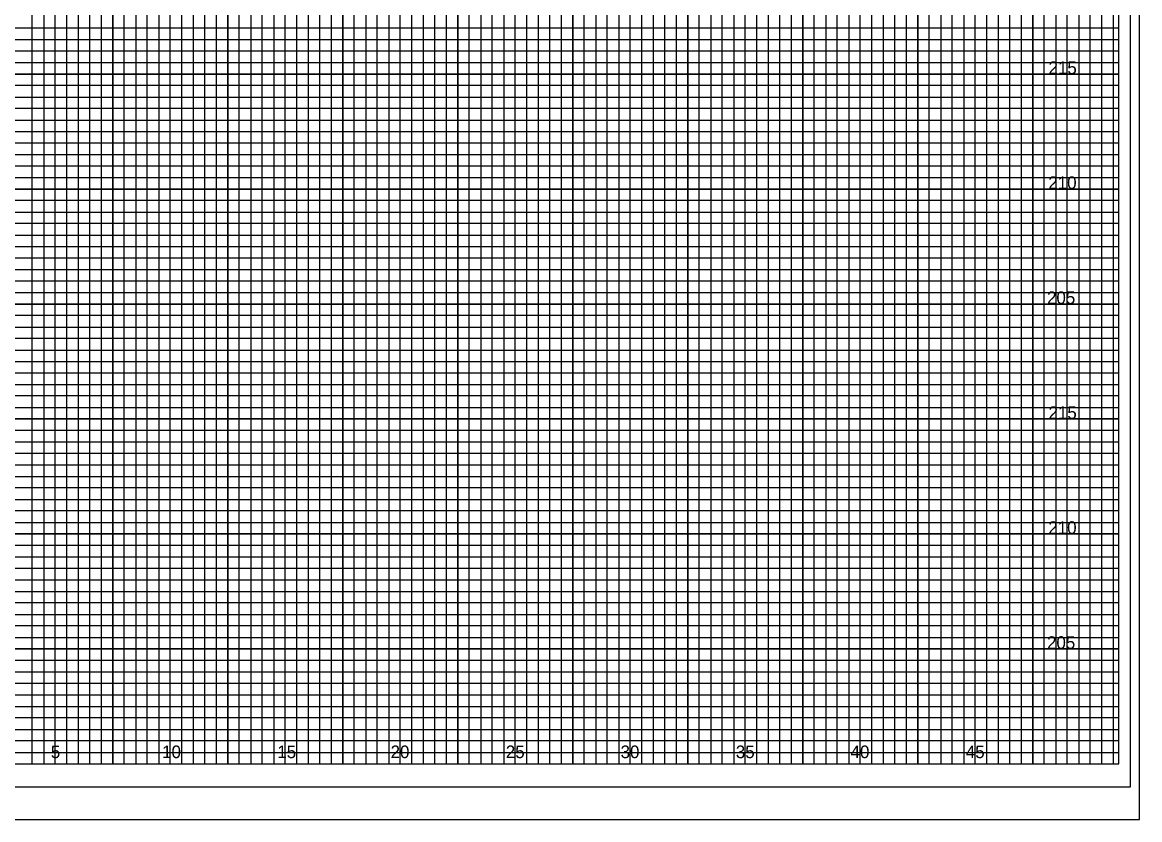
# Model space of a CAD drawing. Extents: x -4 to 103, y -2 to 209.
# Drawn here: x 54.82 to 103.4, y -2.43 to 32.25 of the extents above; entities that cross this region are included whole.
import ezdxf

# ---------------------------------------------------------------- set-up
doc = ezdxf.new("R2010")
doc.units = 0
for name, color, linetype in [('Old_Level_10', 7, 'Continuous'), ('Old_Level_16', 7, 'Continuous'), ('Old_Level_17', 7, 'Continuous'), ('Old_Level_3', 7, 'Continuous'), ('Old_Level_5', 7, 'Continuous'), ('Old_Level_6', 7, 'Continuous'), ('Old_Level_8', 7, 'Continuous'), ('Prop Dimension', 7, 'Continuous'), ('Typical Curb CELL', 7, 'Continuous')]:
    doc.layers.add(name, color=color, linetype=linetype)

msp = doc.modelspace()

# ---------------------------------------------------------------- linework, layer by layer
at = {"layer": 'Old_Level_10'}
for p, q in [((56.25, 0), (56.25, 65)), ((58.75, 0), (58.75, 65)), ((61.25, 0), (61.25, 65)), ((63.75, 0), (63.75, 65)), ((66.25, 0), (66.25, 65)), ((68.75, 0), (68.75, 65)), ((71.25, 0), (71.25, 65)), ((73.75, 0), (73.75, 65)), ((91.25, 0), (91.25, 63.425)), ((93.75, 0), (93.75, 63.425)), ((96.25, 0), (96.25, 63.425)), ((98.75, 0), (98.75, 63.425)), ((101.25, 0), (101.25, 63.425)), ((76.25, 0), (76.25, 62)), ((78.75, 0), (78.75, 62)), ((81.25, 0), (81.25, 62)), ((83.75, 0), (83.75, 62)), ((86.25, 0), (86.25, 62)), ((88.75, 0), (88.75, 62)), ((0, 30), (102.5, 30)), ((0, 27.5), (102.5, 27.5)), ((0, 25), (102.5, 25)), ((0, 22.5), (102.5, 22.5)), ((0, 20), (102.5, 20)), ((0, 17.5), (102.5, 17.5)), ((0, 15), (102.5, 15)), ((0, 12.5), (102.5, 12.5)), ((0, 10), (102.5, 10)), ((0, 7.5), (102.5, 7.5)), ((0, 5), (102.5, 5)), ((0, 2.5), (102.5, 2.5))]:
    msp.add_line(p, q, dxfattribs=at)
at = {"layer": 'Old_Level_17'}
for points in [[(54.75, 0), (55.25, 0), (55.25, 65)], [(55.75, 65), (55.75, 0), (56.75, 0), (56.75, 65)], [(57.25, 65), (57.25, 0), (57.75, 0), (57.75, 65)], [(58.25, 65), (58.25, 0), (59.25, 0), (59.25, 65)], [(59.75, 65), (59.75, 0), (60.25, 0), (60.25, 65)], [(60.75, 65), (60.75, 0), (61.75, 0), (61.75, 65)], [(62.25, 65), (62.25, 0), (62.75, 0), (62.75, 65)], [(63.25, 65), (63.25, 0), (64.25, 0), (64.25, 65)], [(64.75, 65), (64.75, 0), (65.25, 0), (65.25, 65)], [(65.75, 65), (65.75, 0), (66.75, 0), (66.75, 65)], [(67.25, 65), (67.25, 0), (67.75, 0), (67.75, 65)], [(68.25, 65), (68.25, 0), (69.25, 0), (69.25, 65)], [(69.75, 65), (69.75, 0), (70.25, 0), (70.25, 65)], [(70.75, 65), (70.75, 0), (71.75, 0), (71.75, 65)], [(72.25, 65), (72.25, 0), (72.75, 0), (72.75, 65)], [(73.25, 65), (73.25, 0), (74.25, 0), (74.25, 62)], [(89.75, 62), (89.75, 0), (90.25, 0), (90.25, 63.425)], [(90.75, 63.425), (90.75, 0), (91.75, 0), (91.75, 63.425)], [(92.25, 63.425), (92.25, 0), (92.75, 0), (92.75, 63.425)], [(93.25, 63.425), (93.25, 0), (94.25, 0), (94.25, 63.425)], [(94.75, 63.425), (94.75, 0), (95.25, 0), (95.25, 63.425)], [(95.75, 63.425), (95.75, 0), (96.75, 0), (96.75, 63.425)], [(97.25, 63.425), (97.25, 0), (97.75, 0), (97.75, 63.425)], [(98.25, 63.425), (98.25, 0), (99.25, 0), (99.25, 63.425)], [(99.75, 63.425), (99.75, 0), (100.25, 0), (100.25, 63.425)], [(100.25, 63.425), (100.75, 63.425), (100.75, 0), (101.75, 0), (101.75, 63.425), (102.25, 63.425), (102.25, 0)], [(74.75, 62), (74.75, 0), (75.25, 0), (75.25, 62)], [(75.75, 62), (75.75, 0), (76.75, 0), (76.75, 62)], [(77.25, 62), (77.25, 0), (77.75, 0), (77.75, 62)], [(78.25, 62), (78.25, 0), (79.25, 0), (79.25, 62)], [(79.75, 62), (79.75, 0), (80.25, 0), (80.25, 62)], [(80.75, 62), (80.75, 0), (81.75, 0), (81.75, 62)], [(82.25, 62), (82.25, 0), (82.75, 0), (82.75, 62)], [(83.25, 62), (83.25, 0), (84.25, 0), (84.25, 62)], [(84.75, 62), (84.75, 0), (85.25, 0), (85.25, 62)], [(85.75, 62), (85.75, 0), (86.75, 0), (86.75, 62)], [(87.25, 62), (87.25, 0), (87.75, 0), (87.75, 62)], [(88.25, 62), (88.25, 0), (89.25, 0), (89.25, 62)], [(0, 31.5), (102.5, 31.5), (102.5, 32), (0, 32)], [(0, 30.5), (102.5, 30.5), (102.5, 31), (0, 31)], [(0, 29), (102.5, 29), (102.5, 29.5), (0, 29.5)], [(0, 28), (102.5, 28), (102.5, 28.5), (0, 28.5)], [(0, 26.5), (102.5, 26.5), (102.5, 27), (0, 27)], [(0, 25.5), (102.5, 25.5), (102.5, 26), (0, 26)], [(0, 24), (102.5, 24), (102.5, 24.5), (0, 24.5)], [(0, 23), (102.5, 23), (102.5, 23.5), (0, 23.5)], [(0, 21.5), (102.5, 21.5), (102.5, 22), (0, 22)], [(0, 20.5), (102.5, 20.5), (102.5, 21), (0, 21)], [(0, 19), (102.5, 19), (102.5, 19.5), (0, 19.5)], [(0, 18), (102.5, 18), (102.5, 18.5), (0, 18.5)], [(0, 16.5), (102.5, 16.5), (102.5, 17), (0, 17)], [(0, 15.5), (102.5, 15.5), (102.5, 16), (0, 16)], [(0, 14), (102.5, 14), (102.5, 14.5), (0, 14.5)], [(0, 13), (102.5, 13), (102.5, 13.5), (0, 13.5)], [(0, 11.5), (102.5, 11.5), (102.5, 12), (0, 12)], [(0, 10.5), (102.5, 10.5), (102.5, 11), (0, 11)], [(0, 9), (102.5, 9), (102.5, 9.5), (0, 9.5)], [(0, 8), (102.5, 8), (102.5, 8.5), (0, 8.5)], [(0, 6.5), (102.5, 6.5), (102.5, 7), (0, 7)], [(0, 5.5), (102.5, 5.5), (102.5, 6), (0, 6)], [(0, 4), (102.5, 4), (102.5, 4.5), (0, 4.5)], [(0, 3), (102.5, 3), (102.5, 3.5), (0, 3.5)], [(0, 1.5), (102.5, 1.5), (102.5, 2), (0, 2)], [(0, 0.5), (102.5, 0.5), (102.5, 1), (0, 1)]]:
    msp.add_lwpolyline(points, dxfattribs=at)
at = {"layer": 'Old_Level_3'}
msp.add_line((-3.5, -2.425), (103.4, -2.425), dxfattribs=at)
at = {"layer": 'Old_Level_5'}
msp.add_lwpolyline([(103.4, 67.4), (-3.5, 67.4), (-3.5, -2.425), (103.4, -2.425)], close=True, dxfattribs=at)
at = {"layer": 'Old_Level_6'}
msp.add_lwpolyline([(102.5, 65), (0, 65), (0, 0), (102.5, 0)], close=True, dxfattribs=at)
at = {"layer": 'Old_Level_8'}
for points in [[(56.25, 0), (56.25, 65)], [(58.75, 65), (58.75, 0), (61.25, 0), (61.25, 65)], [(63.75, 65), (63.75, 0), (66.25, 0), (66.25, 65)], [(68.75, 65), (68.75, 0), (71.25, 0), (71.25, 65)], [(73.75, 65), (73.75, 0), (76.25, 0), (76.25, 62)], [(88.75, 62), (88.75, 0), (91.25, 0), (91.25, 63.425)], [(93.75, 63.425), (93.75, 0), (96.25, 0), (96.25, 63.425)], [(98.75, 63.425), (98.75, 0), (101.25, 0), (101.25, 63.425)], [(78.75, 62), (78.75, 0), (81.25, 0), (81.25, 62)], [(83.75, 62), (83.75, 0), (86.25, 0), (86.25, 62)], [(0, 27.5), (102.5, 27.5), (102.5, 30), (0, 30)], [(0, 22.5), (102.5, 22.5), (102.5, 25), (0, 25)], [(0, 17.5), (102.5, 17.5), (102.5, 20), (0, 20)], [(0, 12.5), (102.5, 12.5), (102.5, 15), (0, 15)], [(0, 7.5), (102.5, 7.5), (102.5, 10), (0, 10)], [(0, 2.5), (102.5, 2.5), (102.5, 5), (0, 5)]]:
    msp.add_lwpolyline(points, dxfattribs=at)
at = {"layer": 'Typical Curb CELL'}
msp.add_lwpolyline([(103, 66), (-2.8, 66), (-2.8, -1), (103, -1)], close=True, dxfattribs=at)

# ---------------------------------------------------------------- texts
at = {"layer": 'Old_Level_16'}
for s, p in [('5', (56.0574, 0.25)), ('10', (60.8971, 0.25)), ('15', (65.9057, 0.25)), ('20', (70.8312, 0.25)), ('25', (75.8399, 0.25)), ('30', (80.8312, 0.25)), ('35', (85.8399, 0.25)), ('40', (90.8313, 0.25)), ('45', (95.8399, 0.25))]:
    msp.add_text(s, height=0.55, dxfattribs=at).set_placement(p)
at = {"layer": 'Prop Dimension'}
for s, p in [('215', (99.4383, 30)), ('210', (99.4296, 25)), ('205', (99.3724, 20)), ('215', (99.4383, 15)), ('210', (99.4296, 10)), ('205', (99.3724, 5))]:
    msp.add_text(s, height=0.55, dxfattribs=at).set_placement(p)

doc.saveas('drawing.dxf')
